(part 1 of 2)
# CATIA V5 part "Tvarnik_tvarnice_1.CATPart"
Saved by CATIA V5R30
Part number: Tvarnik_tvarnice
Bounding box of the stored display mesh (mm): x -44.4 to 47.6, y -90 to 90, z -90 to 90
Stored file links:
  E:\Bakalarka\Model\Forma_v7\Tvarnik_tvarnice_1.CATPart
  E:\Bakalarka\Model\Sestava_formy_1\Vicko.CATPart
  E:\Bakalarka\Model\Sestava_formy\Tvarnik_tvarnice.CATPart
  E:\Bakalarka\Model\Sestava_formy_1\Sestava_tvarniku_tvarnice.CATProduct
  E:\Bakalarka\Model\Sestava_formy_1\Forma_Sestava_tvarniku_tvarnice.CATPart
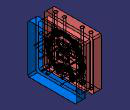
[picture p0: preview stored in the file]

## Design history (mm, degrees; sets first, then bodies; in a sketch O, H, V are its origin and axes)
Body1 (main body)
Body2 "Tvarnik"
  Sketch1 on face of Solid1, origin (1.6, 0, 0), H (0, 1, 0), V (0, 0, 1)
    line L1 (80, 80) -> (80, -80)
    line L2 (80, -80) -> (-80, -80)
    line L3 (-80, -80) -> (-80, 80)
    line L4 (-80, 80) -> (80, 80)
    length L4 = 160
    length L1 = 160
    vertical: L1 V, L3 V
    horizontal: L2 H, L4 H
    equidistance: L1 L3 O, L2 L4 O
  Pad1: profile Sketch1, direction (-1, 0, 0), length 16
  Body3 "Vicko"
    Solid1: linked copy from another document
    Sketch2 on face of Solid1, origin (-0.4, 0, 0), H (0, -1, 0), V (0, 0, 1)
    Pad2: profile Sketch2, direction (-1, 0, 0), up to face of Solid1
    Plane1: type Offset, RefPlane xy-plane, Offset 47, reversed
    Sketch3 on Plane1, origin (0, 0, -47), H (1, 0, 0), V (0, 1, 0)
      line L1 (-2.9, -11.5) -> (-0.8, -11.5)
      line L2 (-0.8, -11.5) -> (-0.8, 11.5)
      line L3 (-0.8, 11.5) -> (-2.9, 11.5)
      line L4 (-2.9, 11.5) -> (-2.9, -11.5)
      reference projected line E1 (-0.8, -2.5) -> (-0.8, 2.5) from edge [end face of Pad2 | face of Pad2]
      reference projected line E2 (-0.4, 11.5) -> (-2.8, 11.5) from edge [face of Solid1 | face of Solid1]
      reference projected line E3 (-0.4, -11.5) -> (-2.8, -11.5) from edge [face of Solid1 | face of Solid1]
      reference projected line E4 (-2.9, 2.4) -> (-2.9, -2.4) from edge [face of Solid1 | face of Solid1]
      distance L2 E1 = 0
      distance L3 E2 = 0
      distance L1 E3 = 0
      distance L4 E4 = 0
      horizontal: L1 H, L3 H
      vertical: L2 V, L4 V
    Pocket1: profile Sketch3, direction (0, 0, 1), length 4
    Fillet1: radius 0.5, on edge [face of Pocket1 | face of Pocket1] (x4)
    Chamfer1: length 0.021, second length 0.4, on edge [face of Pocket1 | face of Pad2]
    Chamfer2: length 0.021, second length 0.4, on edge [face of Pocket1 | face of Pad2]
    Chamfer3: length 0.021, second length 0.4, on edge [face of Pocket1 | face of Pad2]
    Fillet2: radius 0.5, on edge [face of Pocket1 | face of Solid1]
  Remove1: tool Body3
  Sketch4 on start face of Pad1, origin (1.6, 0, 0), H (0, 1, 0), V (0, 0, 1)
    projected arc E1 centre (0, 0) radius 71.425 from (33.2826, 63.1965) to (-30.4134, 64.6263) ccw from edge [face of Solid1 | face of Solid1]
    projected arc E2 centre (-31.265, 66.4359) radius 2 from (-30.8799, 64.4733) to (-30.4134, 64.6263) ccw from edge [face of Solid1 | face of Solid1]
    projected arc E3 centre (-31.265, 66.4359) radius 2 from (-32.3394, 64.749) to (-30.8799, 64.4733) ccw from edge [face of Solid1 | face of Solid1]
    projected arc E4 centre (-35.5625, 59.6882) radius 6 from (-32.3394, 64.749) to (-41.5474, 59.2628) ccw from edge [face of Solid1 | face of Solid1]
    projected arc E5 centre (-43.5423, 59.121) radius 2 from (-42.3563, 57.5107) to (-41.5474, 59.2628) ccw from edge [face of Solid1 | face of Solid1]
    projected arc E6 centre (0, 0) radius 71.425 from (-42.3563, 57.5107) to (-68.5299, 20.1291) ccw from edge [face of Solid1 | face of Solid1]
    projected arc E7 centre (-70.4489, 20.6927) radius 2 from (-69.8997, 18.7696) to (-68.5299, 20.1291) ccw from edge [face of Solid1 | face of Solid1]
    projected arc E8 centre (-68.2522, 13.0002) radius 6 from (-69.8997, 18.7696) to (-71.9052, 8.2404) ccw from edge [face of Solid1 | face of Solid1]
    projected arc E9 centre (-73.1229, 6.6538) radius 2 from (-71.1311, 6.4726) to (-71.9052, 8.2404) ccw from edge [face of Solid1 | face of Solid1]
    projected arc E10 centre (0, 0) radius 71.425 from (-71.1311, 6.4726) to (-64.1739, -31.3568) ccw from edge [face of Solid1 | face of Solid1]
    projected arc E11 centre (0, 0) radius 71.425 from (-64.1739, -31.3568) to (-44.634, -55.7614) ccw from edge [face of Solid1 | face of Solid1]
    projected arc E12 centre (-44.9464, -56.1518) radius 0.5 from (-44.5334, -55.87) to (-44.634, -55.7614) ccw from edge [face of Solid1 | face of Solid1]
    projected line E13 (-44.5334, -55.87) -> (-43.5459, -57.3175) from edge [face of Solid1 | face of Solid1]
    projected arc E14 centre (-43.1328, -57.0357) radius 0.5 from (-43.5459, -57.3175) to (-42.9183, -57.4874) ccw from edge [face of Solid1 | face of Solid1]
    projected line E15 (-42.9183, -57.4874) -> (-42.6019, -57.337) from edge [face of Solid1 | face of Solid1]
    projected arc E16 centre (-42.6448, -57.2467) radius 0.1 from (-42.6019, -57.337) to (-42.5892, -57.3299) ccw from edge [face of Solid1 | face of Solid1]
    projected arc E17 centre (-38.7, -63.15) radius 7 from (-37.0577, -56.3454) to (-42.5892, -57.3299) ccw from edge [face of Solid1 | face of Solid1]
    projected arc E19 centre (-39.7026, -63.67) radius 8 from (-33.5229, -68.7505) to (-31.75, -64.54) ccw from edge [face of Solid1 | face of Solid1]
    projected arc E20 centre (-33.4456, -68.814) radius 0.1 from (-33.5229, -68.7505) to (-33.494, -68.9015) ccw from edge [face of Solid1 | face of Solid1]
    projected line E21 (-33.494, -68.9015) -> (-28.2581, -71.7985) from edge [face of Solid1 | face of Solid1]
    projected line E22 (-25.7474, -73.1876) -> (-28.2581, -71.7985) from edge [face of Solid1 | face of Solid1]
    projected arc E23 centre (-25.7, -67.2) radius 6 from (-25.7, -73.2) to (-19.7, -67.2) ccw from edge [face of Solid1 | face of Solid1]
    projected line E24 (-19.7, -52.2166) -> (-19.7, -67.2) from edge [face of Solid1 | face of Solid1]
    projected arc E25 centre (-12.6167, -52.2166) radius 7.0833 from (-14.8563, -45.4967) to (-19.7, -52.2166) ccw from edge [face of Solid1 | face of Solid1]
    projected arc E26 centre (-12.6167, -52.2166) radius 7.0833 from (-13.7, -45.2166) to (-14.8563, -45.4967) ccw from edge [face of Solid1 | face of Solid1]
    projected arc E27 centre (-1.5593, -117.2) radius 73 from (8.5876, -44.9086) to (-13.7, -45.2166) ccw from edge [face of Solid1 | face of Solid1]
    projected arc E28 centre (-1.5593, -117.2) radius 73 from (12.028, -45.4756) to (8.5876, -44.9086) ccw from edge [face of Solid1 | face of Solid1]
    projected arc E29 centre (10.55, -54.5084) radius 9.15 from (14.5407, -46.2746) to (12.2, -45.5084) ccw from edge [face of Solid1 | face of Solid1]
    projected arc E30 centre (-1.5593, -117.2) radius 73 from (12.2, -45.5084) to (12.028, -45.4756) ccw from edge [face of Solid1 | face of Solid1]
    projected arc E31 centre (10.55, -54.5084) radius 9.15 from (19.7, -54.5084) to (14.5407, -46.2746) ccw from edge [face of Solid1 | face of Solid1]
    projected line E32 (19.7, -54.5084) -> (19.7, -65.95) from edge [face of Solid1 | face of Solid1]
    projected arc E33 centre (26.95, -65.95) radius 7.25 from (19.7, -65.95) to (26.95, -73.2) ccw from edge [face of Solid1 | face of Solid1]
    projected line E34 (26.95, -73.2) -> (27.1807, -73.2) from edge [face of Solid1 | face of Solid1]
    projected line E35 (27.2179, -73.1928) -> (29.0487, -72.4522) from edge [face of Solid1 | face of Solid1]
    projected line E36 (27.2179, -73.1928) -> (27.1999, -73.1995) from edge [face of Solid1 | face of Solid1]
    projected line E37 (27.1999, -73.1995) -> (27.1807, -73.2) from edge [face of Solid1 | face of Solid1]
    projected arc E38 centre (27.2, -65.7) radius 7 from (29.0596, -72.4485) to (34.2, -65.7) ccw from edge [face of Solid1 | face of Solid1]
    projected line E39 (29.054, -72.45) -> (29.0596, -72.4485) from edge [face of Solid1 | face of Solid1]
    projected line E40 (29.0487, -72.4522) -> (29.054, -72.45) from edge [face of Solid1 | face of Solid1]
    projected arc E41 centre (39.6, -65.7) radius 5.4 from (34.6823, -63.4692) to (34.2, -65.7) ccw from edge [face of Solid1 | face of Solid1]
    projected line E42 (34.6907, -63.4503) -> (34.6823, -63.4692) from edge [face of Solid1 | face of Solid1]
    projected arc E43 centre (34.5768, -63.4037) radius 0.123 from (34.6907, -63.4503) to (34.6998, -63.4087) ccw from edge [face of Solid1 | face of Solid1]
    projected line E44 (34.7, -63.3874) -> (34.6998, -63.4087) from edge [face of Solid1 | face of Solid1]
    projected line E45 (34.7, -63.3874) -> (34.7, -62.4295) from edge [face of Solid1 | face of Solid1]
    projected arc E46 centre (0, 0) radius 71.425 from (34.7, -62.4295) to (69.8826, -14.7632) ccw from edge [face of Solid1 | face of Solid1]
    projected arc E47 centre (70.861, -14.9699) radius 1 from (70.1987, -14.2207) to (69.8826, -14.7632) ccw from edge [face of Solid1 | face of Solid1]
    projected line E48 (70.1987, -14.2207) -> (71.6567, -12.9317) from edge [face of Solid1 | face of Solid1]
    projected line E49 (71.6567, -12.9317) -> (72.0071, -12.6219) from edge [face of Solid1 | face of Solid1]
    projected line E50 (72.1405, -12.504) -> (72.0071, -12.6219) from edge [face of Solid1 | face of Solid1]
    projected arc E51 centre (72.4717, -12.8786) radius 0.5 from (72.2645, -12.4235) to (72.1405, -12.504) ccw from edge [face of Solid1 | face of Solid1]
    projected arc E52 centre (69.7785, -6.9628) radius 6 from (72.2645, -12.4235) to (75.4588, -5.0305) ccw from edge [face of Solid1 | face of Solid1]
    projected line E53 (70.9819, 8.13) -> (75.4588, -5.0305) from edge [face of Solid1 | face of Solid1]
    projected arc E54 centre (69.5316, 12.3887) radius 4.4 from (65.7164, 14.5806) to (70.8571, 8.1931) ccw from edge [face of Solid1 | face of Solid1]
    projected line E55 (65.7164, 14.5806) -> (68.6344, 19.6597) from edge [face of Solid1 | face of Solid1]
    projected arc E56 centre (68.5476, 19.7096) radius 0.1001 from (68.6357, 19.662) to (68.6445, 19.7346) ccw from edge [face of Solid1 | face of Solid1]
    projected arc E57 centre (0, 0) radius 71.425 from (68.6438, 19.7372) to (44.8942, 55.5522) ccw from edge [face of Solid1 | face of Solid1]
    projected arc E58 centre (46.1513, 57.1077) radius 2 from (44.1679, 56.8506) to (44.8942, 55.5522) ccw from edge [face of Solid1 | face of Solid1]
    projected arc E59 centre (46.1513, 57.1077) radius 2 from (44.1647, 57.3389) to (44.1679, 56.8506) ccw from edge [face of Solid1 | face of Solid1]
    projected arc E60 centre (38.2049, 58.0324) radius 6 from (44.1647, 57.3389) to (35.2121, 63.2327) ccw from edge [face of Solid1 | face of Solid1]
    projected arc E61 centre (34.2145, 64.9661) radius 2 from (34.4133, 62.976) to (35.2121, 63.2327) ccw from edge [face of Solid1 | face of Solid1]
    projected arc E62 centre (34.2145, 64.9661) radius 2 from (33.2826, 63.1965) to (34.4133, 62.976) ccw from edge [face of Solid1 | face of Solid1]
    line L1 (68.6445, 19.7346) -> (68.6437, 19.7374)
    line L2 (-25.7, -73.2) -> (-25.7474, -73.1876)
    arc A1 centre (70.8987, 8.1188) radius 0.0834 from (70.9741, 8.1546) to (70.8713, 8.1976) ccw
    line L3 (70.8571, 8.1931) -> (70.8673, 8.1964)
    line L4 (70.9819, 8.13) -> (70.9741, 8.1546)
    point P129 (70.8713, 8.1976)
    line L5 (70.8673, 8.1964) -> (70.8713, 8.1976)
    point P130 (70.8713, 8.1976)
    line L6 (68.6344, 19.6597) -> (68.6357, 19.662)
    projected line E63 (-80, -80) -> (80, -80) from edge [face of Pad1 from Sketch1.L2 | start face of Pad1]
    projected line E64 (80, -80) -> (80, 80) from edge [face of Pad1 from Sketch1.L1 | start face of Pad1]
    projected line E65 (80, 80) -> (-80, 80) from edge [face of Pad1 from Sketch1.L4 | start face of Pad1]
    projected line E66 (-80, 80) -> (-80, -80) from edge [face of Pad1 from Sketch1.L3 | start face of Pad1]
    radius A1 = 0.0834
    distance P130 P129 = 0
    tangency: L1 E57, A1 E54, L3 E54
    perpendicularity: L4 L3
    coincidence: L3 P129, P130 E54
  Pocket2: profile Sketch4, direction (-1, 0, 0), length 16
  Sketch5 on end face of Pad1, origin (-14.4, 0, 0), H (0, -1, 0), V (0, 0, 1)
    line L1 (85.4438, 86.0089) -> (85.4438, -86.0089)
    line L2 (85.4438, -86.0089) -> (-85.4438, -86.0089)
    line L3 (-85.4438, -86.0089) -> (-85.4438, 86.0089)
    line L4 (-85.4438, 86.0089) -> (85.4438, 86.0089)
    projected circle E1 centre (35.5625, 59.6882) radius 5.1 from edge [face of Solid1 | start face of Pad1]
    projected circle E2 centre (-38.2049, 58.0324) radius 5.1 from edge [face of Solid1 | start face of Pad1]
    projected circle E3 centre (-70.2785, -7.2128) radius 5.1 from start face of Pad1
    projected circle E4 centre (-26.45, -66.45) radius 5.1 from edge [face of Solid1 | start face of Pad1]
    projected circle E5 centre (26.2, -66.08) radius 5.1 from edge [face of Solid1 | start face of Pad1]
    projected circle E6 centre (68.2522, 13.0002) radius 5.1 from start face of Pad1
    length L4 = 170.8876
    length L1 = 172.0179
    vertical: L1 V, L3 V
    horizontal: L2 H, L4 H
    equidistance: L1 L3 O, L2 L4 O
  Pocket3: profile Sketch5, direction (1, 0, 0), through (limit type 6)
  Sketch6 on end face of Pad1, origin (-14.4, 0, 0), H (0, -1, 0), V (0, 0, 1)
    projected circle E1 centre (68.2522, 13.0002) radius 5.1 from end face of Pad1
    projected circle E2 centre (35.5625, 59.6882) radius 5.1 from end face of Pad1
    projected circle E3 centre (-38.2049, 58.0324) radius 5.1 from end face of Pad1
    projected circle E4 centre (-70.2785, -7.2128) radius 5.1 from end face of Pad1
    projected circle E5 centre (-26.45, -66.45) radius 5.1 from end face of Pad1
    projected circle E6 centre (26.2, -66.08) radius 5.1 from end face of Pad1
  Pocket4: profile Sketch6, direction (1, 0, 0), length 12.7
  Sketch7 on start face of Pad1, origin (1.6, 0, 0), H (0, 1, 0), V (0, 0, 1)
    point P1 (0, 0)
    line L1 (80, 80) -> (80, -80)
    line L2 (80, -80) -> (-80, -80)
    line L3 (-80, -80) -> (-80, 80)
    line L4 (-80, 80) -> (80, 80)
    length L4 = 160
    length L1 = 160
    distance V L1 = 80
    coincidence: P1 H
    vertical: L1 V, L3 V
    horizontal: L2 H, L4 H
    equidistance: L1 L3 P1, L2 L4 P1
  Pad3: profile Sketch7, direction (1, 0, 0), length 16
  Sketch8 on start face of Pad3, origin (1.6, 0, 0), H (0, -1, 0), V (0, 0, 1)
  Pocket5: profile Sketch8, direction (1, 0, 0), length 1
  Fillet3: radius 0.5, on end face of Pocket5
  Fillet4: radius 0.5, on edge [start face of Pad3 | face of Pocket5] (x12)
  Fillet5: radius 0.1, on edge [face of Solid1 | face of Solid1] (x3)
  Fillet6: radius 0.1, on edge [face of Solid1 | face of Solid1] (x3)
  Fillet7: radius 0.1, on edge [face of Solid1 | face of Solid1] (x2)
  Fillet8: radius 0.05, on edge [face of Solid1 | face of Solid1]
  Fillet9: radius 0.1, on edge [face of Solid1 | start face of Pad3] (x2); edge [start face of Pad3 | face of Solid1] (x3)
  Fillet10: radius 0.1, on edge [face of Solid1 | face of Solid1]
  Sketch9 on end face of Pad3, origin (17.6, 0, 0), H (0, 1, 0), V (0, 0, 1)
    line L1 (90, 90) -> (90, -90)
    line L2 (90, -90) -> (-90, -90)
    line L3 (-90, -90) -> (-90, 90)
    line L4 (-90, 90) -> (90, 90)
    length L4 = 180
    length L1 = 180
    vertical: L1 V, L3 V
    horizontal: L2 H, L4 H
    equidistance: L1 L3 O, L2 L4 O
  Pad4: profile Sketch9, direction (1, 0, 0), length 30
  Sketch10 on end face of Pocket4, origin (-1.7, 0, 0), H (0, -1, 0), V (0, 0, 1)
    point P1 (-69.8618, -2.2572)
    line L1 (-67.3618, -1.8448) -> (-67.3618, -2.6696)
    line L2 (-67.3618, -2.6696) -> (-72.3618, -2.6696)
    line L3 (-72.3618, -2.6696) -> (-72.3618, -1.8448)
    line L4 (-72.3618, -1.8448) -> (-67.3618, -1.8448)
    length L4 = 5
    vertical: L1 V, L3 V
    horizontal: L2 H, L4 H
    equidistance: L1 L3 P1, L2 L4 P1
  Pocket6: profile Sketch10, direction (1, 0, 0), length 1
  Sketch11 on start face of Pad3, origin (1.6, 0, 0), H (0, -1, 0), V (0, 0, 1)
    point P1 (-45.5, 54.5)
    point P2 (-64.5, 22.5)
    point P3 (-69.5, 0)
    point P4 (-35.5, -4)
    point P5 (-18, 20)
    point P6 (10, 25)
    point P7 (5, 44.5)
    point P8 (23.5, 54.5)
    point P9 (43, 53.5)
    point P10 (66, 21.5)
    point P11 (60, 15)
    point P12 (45, -10)
    point P13 (35.5, -45)
    point P14 (-30, -57.5)
    point P15 (-35, -53)
    point P16 (-35.5, -33)
    point P17 (-32, 61)
    construction circle A1 centre (35.5, -45) radius 4.5
    construction circle A2 centre (45, -10) radius 4.5
    construction circle A3 centre (66, 21.5) radius 2
    construction circle A4 centre (60, 15) radius 1.15
    construction circle A5 centre (43, 53.5) radius 1.15
    construction circle A6 centre (23.5, 54.5) radius 2
    construction circle A7 centre (5, 44.5) radius 4.5
    construction circle A8 centre (-35.5, -4) radius 2
    construction circle A9 centre (-69.5, 0) radius 2
    construction circle A10 centre (-64.5, 22.5) radius 2
    construction circle A11 centre (-45.5, 54.5) radius 2
    construction circle A12 centre (-18, 20) radius 4.5
    construction circle A13 centre (10, 25) radius 2
    construction circle A14 centre (-35.5, -33) radius 2
    construction circle A15 centre (-35, -53) radius 1.15
    construction circle A16 centre (-30, -57.5) radius 2
    construction line L1 (-85, 90) -> (85, 90)
    construction line L2 (-90, -85) -> (-90, 85)
    reference projected line E1 (-90, 90) -> (90, 90) from edge [start face of Pad4 | face of Pad4 from Sketch9.L4]
    reference projected line E2 (-90, -90) -> (-90, 90) from edge [start face of Pad4 | face of Pad4 from Sketch9.L1]
    reference projected line E3 (90, -90) -> (-90, -90) from edge [start face of Pad4 | face of Pad4 from Sketch9.L2]
    reference projected line E4 (90, 90) -> (90, -90) from edge [start face of Pad4 | face of Pad4 from Sketch9.L3]
    reference projected line E5 (80, -80) -> (-80, -80) from edge [start face of Pad3 | face of Pad3 from Sketch7.L2]
    reference projected line E6 (-80, 80) -> (80, 80) from edge [start face of Pad3 | face of Pad3 from Sketch7.L4]
    reference projected line E7 (80, 80) -> (80, -80) from edge [start face of Pad3 | face of Pad3 from Sketch7.L3]
    distance P17 L1 = 29
    distance P17 L2 = 58
    distance P17 E1 = 29
    distance P17 E2 = 58
    distance P1 E2 = 44.5
    distance P1 E1 = 35.5
    distance P2 E2 = 25.5
    distance P2 E1 = 67.5
    distance P3 E2 = 20.5
    distance P16 E3 = 57
    distance P15 E3 = 37
    distance P14 E3 = 32.5
    distance P14 E2 = 60
    distance P15 E2 = 55
    distance P16 E2 = 54.5
    distance P4 E2 = 54.5
    distance P4 E3 = 86
    distance P13 E3 = 45
    distance P13 E4 = 54.5
    distance P12 E4 = 45
    distance P12 E5 = 70
    distance P11 E4 = 30
    distance P11 E6 = 65
    distance P10 E7 = 14
    distance P10 E6 = 58.5
    distance P9 E6 = 26.5
    distance P9 E7 = 37
    distance P7 E6 = 35.5
    distance P7 E7 = 75
    distance P8 E6 = 25.5
    distance P8 E7 = 56.5
    distance E6 P5 = 60
    distance P5 E2 = 72
    distance P6 E2 = 100
    distance P6 E1 = 65
    concentricity: P1 A11, P2 A10, P3 A9, P4 A8, P5 A12, P6 A13, P7 A7, P8 A6, P9 A5, P10 A3, P11 A4, P12 A2, P13 A1, P14 A16, P15 A15, P16 A14
  DatumSurface1
  DatumCurve1
  DatumSurface2
  DatumCurve2
  DatumSurface3 to DatumSurface8
  DatumCurve3
  DatumSurface9 to DatumSurface11
  DatumCurve4
  DatumSurface12
  DatumCurve5
  DatumSurface13 to DatumSurface17
  DatumCurve6
  DatumSurface18 to DatumSurface20
  DatumCurve7
  DatumSurface21
  DatumSurface22
  DatumCurve8
  DatumCurve9
  DatumSurface23
  DatumSurface24
  DatumCurve10
  DatumSurface25
  Sketch12 on face of Solid1, origin (-0.7, 0, 0), H (0, -1, 0), V (0, 0, 1)
    projected circle E1 centre (35.5, -45) radius 3.5 from face of DatumSurface14
    projected circle E2 centre (45, -10) radius 3.5 from face of DatumSurface15
    projected circle E3 centre (60, 15) radius 1.25 from face of DatumSurface16
    projected circle E4 centre (66, 21.5) radius 2 from face of DatumSurface17
    projected circle E5 centre (43, 53.5) radius 1.25 from edge of DatumCurve6
    projected circle E6 centre (23.5, 54.5) radius 2 from face of DatumSurface18
    projected circle E7 centre (5, 44.5) radius 3.5 from face of DatumSurface19
    projected circle E8 centre (10, 25) radius 3.5 from face of DatumSurface20
    projected circle E9 centre (-18, 20) radius 3.5 from edge of DatumCurve7
    projected circle E10 centre (-35.5, -4) radius 3.5 from face of DatumSurface21
    projected circle E11 centre (-35.5, -33) radius 3.5 from face of DatumSurface22
    projected circle E12 centre (-30, -57.5) radius 1.25 from edge of DatumCurve9
    projected circle E13 centre (-69.5, 0) radius 2 from face of DatumSurface23
    projected circle E14 centre (-64.5, 22.5) radius 2 from face of DatumSurface24
    projected circle E15 centre (-45.5, 54.5) radius 1.25 from edge of DatumCurve10
    projected circle E16 centre (-32, 61) radius 1.25 from face of DatumSurface25
  Pocket7: profile Sketch12, direction (1, 0, 0), through (limit type 6)
  Sketch13 on face of Solid1, origin (-2.9, 0, 0), H (0, -1, 0), V (0, 0, 1)
    projected circle E1 centre (10, 25) radius 3.5 from edge [end face of Pad4 | face of Pocket7 from Sketch12.E8]
  Pocket8: profile Sketch13, direction (1, 0, 0), through (limit type 6)
  DatumSurface26
  DatumCurve11
  DatumCurve12
  DatumSurface27
  DatumCurve13 to DatumCurve23
  DatumSurface28
  Sketch14 on start face of Pad3, origin (1.6, 0, 0), H (0, -1, 0), V (0, 0, 1)
    projected line E1 (11, -44.3767) -> (11, -49.5) from edge of DatumCurve14
    projected line E2 (11, -44.7682) -> (11, -49.5) from edge of DatumCurve14
    projected line E3 (11, -49.5) -> (11, -50) from edge of DatumCurve16
    projected line E4 (-12, -49.5) -> (-12, -44.8917) from edge of DatumCurve22
    projected line E5 (-12, -49.5) -> (-12, -45.3604) from edge of DatumCurve22
    projected line E6 (-12, -50) -> (-12, -49.5) from edge of DatumCurve23
    line L1 (11, -50) -> (-12, -50)
    projected arc E7 centre (1.3665, -117.1471) radius 73.195 from (14.49, -45.1382) to (-12.8672, -45.3494) ccw from edge [face of Solid1 | face of Solid1]
    projected line E9 (-10.916, -45.1704) -> (-11.2903, -45.2313) from edge [face of Fillet2 | face of Solid1]
    projected arc E10 centre (1.3665, -117.1471) radius 73.0172 from (10.9346, -44.7596) to (-10.916, -45.1704) ccw from edge [face of Fillet2 | face of Solid1]
    line L2 (-11.5, -45.2623) -> (-12, -45.3604)
    point P17 (-12, -45.3604)
    line L3 (10.9346, -44.7596) -> (11, -44.7682)
    point P18 (11, -44.7682)
    horizontal: L1 H
    tangency: L2 E10, L3 E10
    coincidence: P17 E4, P18 E1
  Pad5: profile Sketch14, direction (-1, 0, 0), up to face of DatumSurface28
  Fillet11: radius 0.5, on edge [end face of Pad5 | face of Pad5 from Sketch14.L1]; edge [start face of Pad3 | face of Pad5 from Sketch14.L1]
  DatumSurface29
  DatumSurface30
  Sketch15 on face of Solid1, origin (-2.9, 0, 0), H (0, -1, 0), V (0, 0, 1)
    projected circle E1 centre (10, -12) radius 3 from face of DatumSurface29
    projected circle E2 centre (2, -31) radius 3 from face of DatumSurface30
  Pocket9: profile Sketch15, direction (1, 0, 0), length 100
  Chamfer4: length 5, angle 45, on edge [face of Pad4 from Sketch9.L3 | face of Pad4 from Sketch9.L4]; edge [face of Pad4 from Sketch9.L4 | face of Pad4 from Sketch9.L1]; edge [face of Pad3 from Sketch7.L4 | face of Pad3 from Sketch7.L1]; edge [face of Pad3 from Sketch7.L3 | face of Pad3 from Sketch7.L4]; edge [face of Pad3 from Sketch7.L2 | face of Pad3 from Sketch7.L3]; edge [face of Pad4 from Sketch9.L2 | face of Pad4 from Sketch9.L3]; edge [face of Pad4 from Sketch9.L1 | face of Pad4 from Sketch9.L2]; edge [face of Pad3 from Sketch7.L1 | face of Pad3 from Sketch7.L2]
  Sketch16 on face of Pad3 from Sketch7.L2, origin (0, 0, -80), H (1, 0, 0), V (0, -1, 0)
    point P1 (9.6, 53.5)
    circle A1 centre (9.6, -55) radius 5
    point P2 (9.6, -55)
    reference projected line E1 (17.6, 90) -> (17.6, -90) from edge [start face of Pad4 | face of Pad4 from Sketch9.L2]
    reference projected line E2 (1.6, 80) -> (1.6, -80) from edge [start face of Pad3 | face of Pad3 from Sketch7.L2]
    reference projected line E3 (1.6, -80) -> (17.6, -80) from edge [face of Pad3 from Sketch7.L1 | face of Chamfer4]
    reference projected line E4 (1.6, 80) -> (17.6, 80) from edge [face of Chamfer4 | face of Pad3 from Sketch7.L3]
    radius A1 = 5
    distance P1 E1 = 8
    distance P2 E2 = 8
    distance P2 E3 = 25
    distance E4 P1 = 26.5
  Pocket10: profile Sketch16, direction (0, 0, 1), through (limit type 6)
  Sketch17 on face of Pad3 from Sketch7.L1, origin (0, 80, 0), H (-1, 0, 0), V (0, 0, 1)
    circle A1 centre (-9.6, 34.5) radius 5
    point P1 (-9.6, 34.5)
    circle A2 centre (-9.6, -22) radius 5
    point P2 (-9.6, -22)
    point P3 (-9.6, -52)
    point P4 (-9.6, 8)
    reference projected line E1 (-1.6, -80) -> (-1.6, 80) from edge [start face of Pad3 | face of Pad3 from Sketch7.L1]
    reference projected line E2 (-1.6, -80) -> (-17.6, -80) from edge [face of Chamfer4 | face of Pad3 from Sketch7.L2]
    radius A2 = 5
    radius A1 = 5
    distance P1 E1 = 8
    distance P4 E1 = 8
    distance P2 E1 = 8
    distance P3 E1 = 8
    distance P3 E2 = 28
    distance P3 P2 = 30
    distance P4 P2 = 30
    distance P4 P1 = 26.5
  Pocket11: profile Sketch17, direction (0, -1, 0), through (limit type 3)
  Sketch18 on face of Pad3 from Sketch7.L1, origin (0, 80, 0), H (-1, 0, 0), V (0, 0, 1)
    construction circle A1 centre (-9.6, -45) radius 5
    point P1 (-9.6, -45)
    reference projected line E1 (-1.6, -80) -> (-1.6, 80) from edge [start face of Pad3 | face of Pad3 from Sketch7.L1]
    reference projected line E2 (-1.6, -80) -> (-17.6, -80) from edge [face of Chamfer4 | face of Pad3 from Sketch7.L2]
    point P2 (-9.6, -45)
    radius A1 = 5
    distance P1 E1 = 8
    distance E2 P1 = 35
    coincidence: P2 P1
  Sketch19 on face of Pad3 from Sketch7.L1, origin (9.6, 80, -45), H (1, 0, 0), V (0, 0, -1)
    point P1 (0, 0)
    reference projected point E1 (0, 0) from Sketch18.P2
    coincidence: E1 P1
  Hole1: placed by Sketch19, at (9.6, 80, -45) direction (0, -1, 0), diameter 10, depth 95, V-bottom angle 120
  Sketch20 on face of Pad3 from Sketch7.L1, origin (9.6, 80, -45), H (1, 0, 0), V (0, 0, -1)
    point P1 (0, 0)
    reference projected point E1 (0, 0) from Sketch18.P2
    coincidence: E1 P1
  Hole2: placed by Sketch20, at (9.6, 80, -45) direction (0, -1, 0), diameter 10.376, depth 8, V-bottom angle 120, threaded "M12x1.5", thread diameter 12, thread depth 8, pitch 1.5
  Sketch21 on face of Pad3 from Sketch7.L1, origin (0, 80, 0), H (-1, 0, 0), V (0, 0, 1)
    point P1 (-9.6, 34.5)
    point P2 (-9.6, 8)
    point P3 (-9.6, -22)
    construction circle A1 centre (-9.6, -22) radius 5
    construction circle A2 centre (-9.6, 8) radius 5
    construction circle A3 centre (-9.6, 34.5) radius 5
    concentricity: P1 A3, P2 A2, P3 A1
  Sketch22 on face of Pad3 from Sketch7.L4, origin (0, 0, 80), H (1, 0, 0), V (0, 1, 0)
    point P1 (9.6, -53.5)
    point P2 (9.6, 55)
    construction circle A1 centre (9.6, 55) radius 5
    construction circle A2 centre (9.6, -53.5) radius 5
    concentricity: P1 A2, P2 A1
  Sketch23 on face of Pad3 from Sketch7.L3, origin (0, -80, 0), H (1, 0, 0), V (0, 0, 1)
    projected point E1 (9.6, 34.5) from Sketch21.P1
    projected point E2 (9.6, 8) from Sketch21.P2
    projected point E3 (9.6, -22) from Sketch21.P3
  DatumCurve24
  DatumCurve25
  DatumSurface31
  DatumCurve26
  Sketch24 on face of Pad3 from Sketch7.L4, origin (0, 0, 80), H (1, 0, 0), V (0, 1, 0)
    circle A1 centre (9.6, -125) radius 6
    circle A2 centre (9.6, -233.5) radius 6
    reference projected line E1 (1.6, -105) -> (1.6, -255) from edge of DatumCurve24
    reference projected line E2 (1.6, -255) -> (17.6, -255) from edge of DatumCurve25
    reference intersected curve E3 from face of DatumSurface31
    reference projected line E4 (1.6, -100) -> (17.6, -100) from edge of DatumCurve26
    radius A2 = 6
    distance A2 E1 = 2
    distance A2 E2 = 27.5
    radius A1 = 6
    distance A1 E3 = 2
    distance A1 E4 = 19
  Pocket12: profile Sketch24, direction (0, 0, -1), length 1
  Plane2: stored without definition
  Mirror1: of Pocket12, about Plane2
  DatumCurve27
  DatumCurve28
  Sketch25 on face of Pad3 from Sketch7.L1, origin (0, 80, 0), H (-1, 0, 0), V (0, 0, 1)
    construction circle A1 centre (-9.6, 10) radius 5
    point P1 (-9.6, 10)
    reference projected line E1 (-1.6, -80) -> (-1.6, 80) from edge [start face of Pad3 | face of Pad3 from Sketch7.L1]
    reference projected line E2 (-1.6, 80) -> (-17.6, 80) from edge [face of Pad3 from Sketch7.L4 | face of Chamfer4]
    point P2 (-9.6, 10)
    reference projected circle E3 centre (-9.6, 34.5) radius 5 from edge [face of Pad3 from Sketch7.L1 | face of Pocket11 from Sketch17.A1]
    reference projected circle E4 centre (-9.6, -22) radius 5 from edge [face of Pad3 from Sketch7.L1 | face of Pocket11 from Sketch17.A2]
    reference projected arc E5 centre (-9.6, -45) radius 5.19 from (-9.6, -50.19) to (-9.6, -39.81) ccw from edge of DatumCurve27
    point P7 (-9.6, 34.5)
    point P8 (-9.6, -22)
    point P9 (-9.6, -45)
    radius A1 = 5
    distance P1 E1 = 8
    distance P1 E2 = 70
    coincidence: P2 P1
    concentricity: P7 E3, P8 E4, P9 E5
  Sketch26 on face of Pad3 from Sketch7.L1, origin (9.6, 80, 8.0002), H (1, 0, 0), V (0, 0, -1)
    point P1 (0, -1.9998)
    reference projected point E1 (0, -1.9998) from Sketch25.P2
    coincidence: E1 P1
  Hole3: placed by Sketch26, at (9.6, 80, 10) direction (0, -1, 0), diameter 10, depth 105, V-bottom angle 120
  Sketch27 on face of Pad3 from Sketch7.L4, origin (0, 0, 80), H (1, 0, 0), V (0, 1, 0)
    construction circle A1 centre (9.6, -34) radius 5
    point P1 (9.6, -34)
    reference projected point E1 (9.6, 55) from axis of face of Pocket10 from Sketch16.A1
    reference projected line E2 (1.6, -80) -> (17.6, -80) from edge [face of Pad3 from Sketch7.L3 | face of Chamfer4]
    point P2 (9.6, -34)
    radius A1 = 5
    distance P1 E1 H = 0
    distance E2 P1 = 46
    coincidence: P2 P1
  Sketch28 on face of Pad3 from Sketch7.L4, origin (9.6, -34, 80), H (1, 0, 0), V (0, 1, 0)
    point P1 (0, 0)
    reference projected point E1 (0, 0) from Sketch27.P2
    coincidence: E1 P1
  Hole4: placed by Sketch28, at (9.6, -34, 80) direction (0, 0, -1), diameter 10, depth 102, V-bottom angle 120
  DatumCurve29
  Sketch29 on face of Pad3 from Sketch7.L2, origin (0, 0, -80), H (1, 0, 0), V (0, -1, 0)
    reference projected circle E1 centre (9.6, 53.5) radius 5 from edge of DatumCurve29
    point P1 (9.6, 53.5)
    concentricity: P1 E1
  Sketch30 on face of Pad3 from Sketch7.L2, origin (9.6, -53.5, -80), H (1, 0, 0), V (0, -1, 0)
    point P1 (0, 0)
    reference projected point E1 (0, 0) from Sketch29.P1
    coincidence: E1 P1
  Hole5: placed by Sketch30, at (9.6, -53.5, -80) direction (0, 0, 1), diameter 10, depth 58, V-bottom angle 120
  DatumCurve30
  Sketch31 on face of Pad3 from Sketch7.L2, origin (0, 0, -80), H (1, 0, 0), V (0, -1, 0)
    projected circle E1 centre (9.6, 53.5) radius 6 from edge of DatumCurve30
  Pocket13: profile Sketch31, direction (0, 0, 1), length 1
  Sketch32 on face of Pad3 from Sketch7.L4, origin (0, 0, 80), H (1, 0, 0), V (0, 1, 0)
    reference projected circle E1 centre (9.6, 55) radius 5 from edge [face of Pocket10 from Sketch16.A1 | face of Pad3 from Sketch7.L4]
    reference projected circle E2 centre (9.6, -34) radius 5 from edge [face of Hole4 | face of Pad3 from Sketch7.L4]
    point P1 (9.6, -34)
    point P2 (9.6, 55)
    concentricity: P1 E2, P2 E1
  Sketch33 on face of Pad3 from Sketch7.L3, origin (0, -80, 0), H (1, 0, 0), V (0, 0, 1)
    reference projected circle E1 centre (9.6, 34.5) radius 5 from face of Pocket11 from Sketch17.A1
    reference projected circle E2 centre (9.6, -22) radius 5 from face of Pocket11 from Sketch17.A2
    point P1 (9.6, -22)
    point P2 (9.6, 34.5)
    concentricity: P1 E2, P2 E1
  Sketch34 on face of Pad3 from Sketch7.L3, origin (9.6, -80, 34.5), H (1, 0, 0), V (0, 0, 1)
    point P1 (0, 0)
    reference projected point E1 (0, 0) from Sketch33.P2
    coincidence: E1 P1
  Hole6: placed by Sketch34, at (9.6, -80, 34.5) direction (0, 1, 0), diameter 10.647, depth 43, V-bottom angle 120, threaded "M12x1.25", thread diameter 12, thread depth 31, pitch 1.25
  Sketch35 on face of Pad3 from Sketch7.L3, origin (9.6, -80, -22), H (1, 0, 0), V (0, 0, 1)
    point P1 (0, 0)
    reference projected point E1 (0, 0) from Sketch33.P1
    coincidence: E1 P1
  Hole7: placed by Sketch35, at (9.6, -80, -22) direction (0, 1, 0), diameter 10.647, depth 25, V-bottom angle 120, threaded "M12x1.25", thread diameter 12, thread depth 22, pitch 1.25
  Sketch36 on face of Pad3 from Sketch7.L4, origin (9.6, -34, 80), H (1, 0, 0), V (0, 1, 0)
    point P1 (0, 0)
    reference projected point E1 (0, 0) from Sketch32.P1
    coincidence: E1 P1
  Hole8: placed by Sketch36, at (9.6, -34, 80) direction (0, 0, -1), diameter 10.647, depth 43, V-bottom angle 120, threaded "M12x1.25", thread diameter 12, thread depth 41, pitch 1.25
  Sketch37 on face of Pad3 from Sketch7.L4, origin (9.6, 55, 80), H (1, 0, 0), V (0, 1, 0)
    point P1 (0, 0)
    reference projected point E1 (0, 0) from Sketch32.P2
    coincidence: E1 P1
  Hole9: placed by Sketch37, at (9.6, 55, 80) direction (0, 0, -1), diameter 10.647, depth 43, V-bottom angle 120, threaded "M12x1.25", thread diameter 12, thread depth 41, pitch 1.25
  Sketch38 on face of Pad3 from Sketch7.L1, origin (9.6, 80, 34.5), H (1, 0, 0), V (0, 0, -1)
    point P1 (0, 0)
    reference projected point E1 (0, 0) from Sketch25.P7
    coincidence: E1 P1
  Hole10: placed by Sketch38, at (9.6, 80, 34.5) direction (0, -1, 0), diameter 10.647, depth 22, V-bottom angle 120, threaded "M12x1.25", thread diameter 12, thread depth 20, pitch 1.25
  Sketch39 on face of Pad3 from Sketch7.L1, origin (9.6, 80, 10), H (1, 0, 0), V (0, 0, -1)
    point P1 (0, 0)
    reference projected point E1 (0, 0) from Sketch25.P2
    coincidence: E1 P1
  Hole11: placed by Sketch39, at (9.6, 80, 10) direction (0, -1, 0), diameter 10.647, depth 12, V-bottom angle 120, threaded "M12x1.25", thread diameter 12, thread depth 10, pitch 1.25
  Sketch40 on face of Pad3 from Sketch7.L1, origin (9.6, 80, -45), H (1, 0, 0), V (0, 0, -1)
    point P1 (0, 0)
    reference projected point E1 (0, 0) from Sketch25.P9
    coincidence: E1 P1
  Hole12: placed by Sketch40, at (9.6, 80, -45) direction (0, -1, 0), diameter 10.647, depth 12, V-bottom angle 120, threaded "M12x1.25", thread diameter 12, thread depth 10, pitch 1.25
  Sketch41 on face of Pad3 from Sketch7.L1, origin (9.6, 80, -22), H (1, 0, 0), V (0, 0, -1)
    point P1 (0, 0)
    reference projected point E1 (0, 0) from Sketch25.P8
    coincidence: E1 P1
  Hole13: placed by Sketch41, at (9.6, 80, -22) direction (0, -1, 0), diameter 10.647, depth 22, V-bottom angle 120, threaded "M12x1.25", thread diameter 12, thread depth 21, pitch 1.25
